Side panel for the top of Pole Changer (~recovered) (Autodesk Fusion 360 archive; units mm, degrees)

design "Side panel for the top of Pole Changer" references "autodesk 3ax table xy head z"
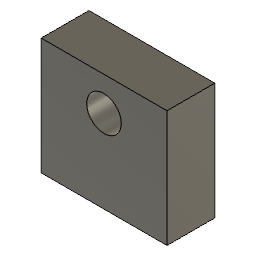
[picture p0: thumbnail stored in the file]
part number: 2026-03-06-14-36-18-397
sketch "Sketch1" plane through (0, 0, 0) normal (0, 0, 1) x axis (1, 0, 0)
  line L1 (32.385, 0) -> (0, 0)
  line L2 (32.385, 12.319) -> (32.385, 0)
  line L3 (0, 12.319) -> (32.385, 12.319)
  line L4 (0, 0) -> (0, 12.319)
  point P1 (0, 0)
  point P2 (0, 0)
  point P3 (32.385, 0)
  point P5 (0, 12.319)
  horizontal L1
  vertical L2
  horizontal L3
  vertical L4
  coincident P1 P2
  dimension "d1" distance P2 P3 = 32.385
  dimension "d2" distance P2 P5 = 12.319
extrude "Extrude1" new body sketch "Sketch1" along normal blind 30.0482
sketch "Sketch2" plane through (0, 0, 0) normal (0, -1, 0) x axis (1, 0, 0)
  line L1 (32.385, 0) -> (0, 0)
  line L2 (32.385, 30.0482) -> (32.385, 0)
  line L3 (0, 30.0482) -> (32.385, 30.0482)
  line L4 (0, 0) -> (0, 30.0482)
  circle C1 centre (16.1726, 21.3291) radius 4.445
  dimension "d5" diameter C1 = 8.89
extrude "Extrude2" cut sketch "Sketch2" profile of C1 against normal blind 12.319

design "autodesk 3ax table xy head z"
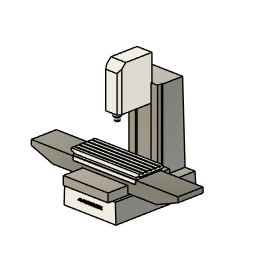
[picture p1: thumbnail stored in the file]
named bodies: "x_axis_table", "y_axis_table", "z_axis_head", "Base"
